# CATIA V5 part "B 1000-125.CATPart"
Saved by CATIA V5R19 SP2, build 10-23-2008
Part number: B 1000-125
Bounding box of the stored display mesh (mm): x -24.865 to 24.865, y -24.997 to 24.997, z 0 to 345
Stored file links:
  C:\Users\Bora\Desktop\3D Katı model\B serisi\B 1000\B 1000-125.CATPart
  C:\Program Files\Dassault Systemes\B19\intel_a\reffiles\standard\MetricThickPitch.txt
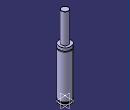
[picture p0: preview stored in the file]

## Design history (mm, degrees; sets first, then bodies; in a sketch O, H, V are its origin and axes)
Body1 (main body)
  Sketch1 on yz-plane, origin (0, 0, 0), H (0, 1, 0), V (0, 0, 1)
    point P1 (25, 204.5)
    point P2 (25, 200.5)
    point P3 (25, 204.5)
    point P6 (25, 200.5)
    point P9 (15, 344)
    point P11 (15, 344)
    arc A1 centre (25, 202.5) radius 2 from (25, 204.5) to (25, 200.5) ccw
    line L1 (25, 204.5) -> (25, 217)
    line L2 (25, 13) -> (25, 200.5)
    line L3 (21.5, 13) -> (21.5, 8)
    arc A2 centre (14, 344) radius 1 from (15, 344) to (14, 345) ccw
    line L4 (15, 344) -> (15, 217)
    line L5 (25, 0) -> (25, 8)
    line L6 (14, 345) -> (0, 345)
    point P15 (0, 345)
    line L7 (15, 217) -> (25, 217)
    line L8 (0, 0) -> (25, 0)
    line L9 (21.5, 13) -> (25, 13)
    line L10 (21.5, 8) -> (25, 8)
    coincidence: P15 V, P1 P3, P2 P6, P9 P11
    tangency: L6 A2
    horizontal: L7 H, L8 H, L9 H, L10 H
  Shaft1: profile Sketch1, axis Sketch1.V, angle 360
  Sketch2 on face of Shaft1 from Sketch1.L8, origin (0, 0, 0), H (1, 0, 0), V (0, -1, 0)
    point P1 (10, 0)
    distance P1 V = 10
  Hole1: placed by Sketch2, at (10, 0, 0) direction (0, 0, 1), diameter 6.647, depth 13, threaded "M8", thread diameter 8, thread depth 13, pitch 1.25
  CircPattern1: of Hole1, instances 2, angular step 180, axis from xy-plane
